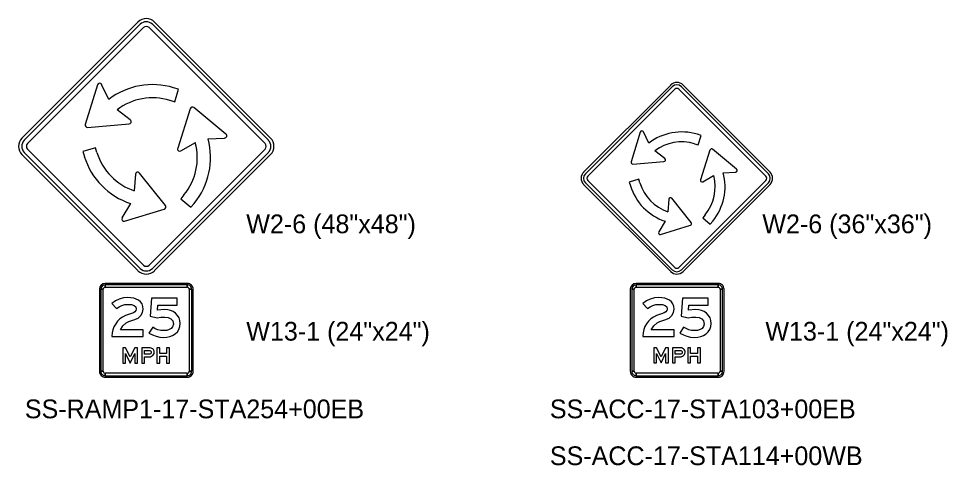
# Model space of a CAD drawing. Extents: x 620856.8 to 620948.6, y 415598.8 to 415658.2.
# Drawn here: x 620856.81 to 620876.63, y 415601 to 415610.53 of the extents above; entities that cross this region are included whole.
import ezdxf

# ---------------------------------------------------------------- set-up
doc = ezdxf.new("R2010")
doc.units = 0
doc.layers.add('SIGNS', color=7, linetype='Continuous')

msp = doc.modelspace()

# ---------------------------------------------------------------- linework, layer by layer
at = {"layer": 'SIGNS'}
for p, q in [((620856.878, 415607.977), (620859.353, 415610.452)), ((620856.926, 415607.93), (620859.4, 415610.405)), ((620859.471, 415610.334), (620856.996, 415607.859)), ((620862.064, 415607.859), (620859.589, 415610.334)), ((620859.66, 415610.405), (620862.135, 415607.93)), ((620859.707, 415610.452), (620862.182, 415607.977)), ((620858.489, 415609.113), (620858.229, 415608.266)), ((620858.489, 415609.113), (620858.229, 415608.266)), ((620858.73, 415608.799), (620858.578, 415609.12)), ((620858.73, 415608.799), (620858.578, 415609.12)), ((620868.863, 415607.252), (620870.72, 415609.108)), ((620868.899, 415607.216), (620870.755, 415609.072)), ((620870.808, 415609.019), (620868.952, 415607.163)), ((620872.752, 415607.163), (620870.896, 415609.019)), ((620870.949, 415609.072), (620872.805, 415607.216)), ((620870.985, 415609.108), (620872.841, 415607.252)), ((620859.188, 415608.363), (620858.907, 415608.58)), ((620859.188, 415608.363), (620858.907, 415608.58)), ((620860.47, 415608.603), (620860.2, 415607.759)), ((620860.47, 415608.603), (620860.2, 415607.759)), ((620861.231, 415608.061), (620860.547, 415608.626)), ((620861.231, 415608.061), (620860.547, 415608.626)), ((620858.279, 415608.204), (620859.163, 415608.277)), ((620858.279, 415608.204), (620859.163, 415608.277)), ((620860.847, 415607.959), (620861.202, 415607.976)), ((620860.847, 415607.959), (620861.202, 415607.976)), ((620870.071, 415608.104), (620869.876, 415607.468)), ((620870.071, 415608.104), (620869.876, 415607.468)), ((620870.252, 415607.868), (620870.138, 415608.109)), ((620870.252, 415607.868), (620870.138, 415608.109)), ((620856.996, 415607.741), (620859.471, 415605.266)), ((620859.589, 415605.266), (620862.064, 415607.741)), ((620860.27, 415607.703), (620860.577, 415607.879)), ((620860.27, 415607.703), (620860.577, 415607.879)), ((620872.127, 415607.315), (620871.615, 415607.738)), ((620872.127, 415607.315), (620871.615, 415607.738)), ((620859.353, 415605.149), (620856.878, 415607.623)), ((620859.4, 415605.196), (620856.926, 415607.671)), ((620862.135, 415607.671), (620859.66, 415605.196)), ((620862.182, 415607.623), (620859.707, 415605.149)), ((620870.596, 415607.541), (620870.385, 415607.703)), ((620870.596, 415607.541), (620870.385, 415607.703)), ((620871.557, 415607.721), (620871.354, 415607.088)), ((620871.557, 415607.721), (620871.354, 415607.088)), ((620869.914, 415607.422), (620870.576, 415607.476)), ((620869.914, 415607.422), (620870.576, 415607.476)), ((620859.297, 415607.204), (620859.275, 415606.85)), ((620859.297, 415607.204), (620859.275, 415606.85)), ((620859.939, 415606.541), (620859.383, 415607.231)), ((620859.939, 415606.541), (620859.383, 415607.231)), ((620871.407, 415607.046), (620871.637, 415607.178)), ((620871.407, 415607.046), (620871.637, 415607.178)), ((620871.84, 415607.238), (620872.106, 415607.251)), ((620871.84, 415607.238), (620872.106, 415607.251)), ((620870.72, 415605.13), (620868.863, 415606.986)), ((620870.755, 415605.166), (620868.899, 415607.022)), ((620868.952, 415607.075), (620870.808, 415605.219)), ((620870.896, 415605.219), (620872.752, 415607.075)), ((620872.805, 415607.022), (620870.949, 415605.166)), ((620872.841, 415606.986), (620870.985, 415605.13)), ((620859.193, 415606.581), (620859.012, 415606.275)), ((620859.193, 415606.581), (620859.012, 415606.275)), ((620870.678, 415606.672), (620870.661, 415606.406)), ((620870.678, 415606.672), (620870.661, 415606.406)), ((620871.159, 415606.174), (620870.742, 415606.692)), ((620871.159, 415606.174), (620870.742, 415606.692)), ((620859.068, 415606.204), (620859.915, 415606.464)), ((620859.068, 415606.204), (620859.915, 415606.464)), ((620870.599, 415606.204), (620870.464, 415605.975)), ((620870.599, 415606.204), (620870.464, 415605.975)), ((620870.505, 415605.922), (620871.141, 415606.117)), ((620870.505, 415605.922), (620871.141, 415606.117)), ((620858.53, 415604.752), (620858.53, 415603.002)), ((620858.561, 415604.752), (620858.613, 415604.752)), ((620860.405, 415604.877), (620858.655, 415604.877)), ((620858.655, 415604.794), (620858.655, 415604.846)), ((620860.405, 415604.846), (620860.405, 415604.794)), ((620860.447, 415604.752), (620860.499, 415604.752)), ((620860.53, 415603.002), (620860.53, 415604.752)), ((620869.859, 415604.753), (620869.859, 415603.003)), ((620869.89, 415604.753), (620869.943, 415604.753)), ((620871.734, 415604.878), (620869.984, 415604.878)), ((620869.984, 415604.794), (620869.984, 415604.846)), ((620871.734, 415604.846), (620871.734, 415604.794)), ((620871.776, 415604.753), (620871.828, 415604.753)), ((620871.859, 415603.003), (620871.859, 415604.753)), ((620858.613, 415603.002), (620858.561, 415603.002)), ((620860.499, 415603.002), (620860.447, 415603.002)), ((620869.943, 415603.003), (620869.89, 415603.003)), ((620871.828, 415603.003), (620871.776, 415603.003)), ((620858.655, 415602.909), (620858.655, 415602.961)), ((620858.655, 415602.877), (620860.405, 415602.877)), ((620860.405, 415602.961), (620860.405, 415602.909)), ((620869.984, 415602.909), (620869.984, 415602.961)), ((620869.984, 415602.878), (620871.734, 415602.878)), ((620871.734, 415602.961), (620871.734, 415602.909))]:
    msp.add_line(p, q, dxfattribs=at)
for points in [[(620860.031, 415608.782), (620860.136, 415608.75), (620860.218, 415609.019), (620860.114, 415609.051)], [(620860.031, 415608.782), (620860.136, 415608.75), (620860.218, 415609.019), (620860.114, 415609.051)], [(620871.228, 415607.855), (620871.306, 415607.831), (620871.368, 415608.033), (620871.29, 415608.057)], [(620871.228, 415607.855), (620871.306, 415607.831), (620871.368, 415608.033), (620871.29, 415608.057)], [(620858.478, 415607.668), (620858.446, 415607.772), (620858.177, 415607.689), (620858.209, 415607.585)], [(620858.478, 415607.668), (620858.446, 415607.772), (620858.177, 415607.689), (620858.209, 415607.585)], [(620870.063, 415607.02), (620870.039, 415607.098), (620869.837, 415607.036), (620869.861, 415606.958)], [(620870.063, 415607.02), (620870.039, 415607.098), (620869.837, 415607.036), (620869.861, 415606.958)], [(620860.334, 415606.763), (620860.264, 415606.679), (620860.481, 415606.5), (620860.551, 415606.584)], [(620860.334, 415606.763), (620860.264, 415606.679), (620860.481, 415606.5), (620860.551, 415606.584)], [(620871.455, 415606.341), (620871.403, 415606.278), (620871.566, 415606.144), (620871.618, 415606.207)], [(620871.455, 415606.341), (620871.403, 415606.278), (620871.566, 415606.144), (620871.618, 415606.207)], [(620859.432, 415603.179), (620859.489, 415603.179), (620859.489, 415603.31), (620859.585, 415603.31), (620859.617, 415603.313), (620859.645, 415603.322), (620859.667, 415603.337), (620859.684, 415603.359), (620859.695, 415603.383), (620859.699, 415603.408), (620859.697, 415603.429), (620859.691, 415603.447), (620859.681, 415603.464), (620859.668, 415603.479), (620859.652, 415603.491), (620859.634, 415603.499), (620859.614, 415603.505), (620859.592, 415603.506), (620859.432, 415603.506), (620859.432, 415603.179)], [(620859.489, 415603.365), (620859.489, 415603.449), (620859.587, 415603.449), (620859.606, 415603.446), (620859.622, 415603.438), (620859.633, 415603.424), (620859.637, 415603.407), (620859.633, 415603.39), (620859.623, 415603.377), (620859.608, 415603.368), (620859.59, 415603.365), (620859.489, 415603.365)], [(620870.761, 415603.18), (620870.819, 415603.18), (620870.819, 415603.31), (620870.914, 415603.31), (620870.946, 415603.313), (620870.974, 415603.322), (620870.996, 415603.338), (620871.013, 415603.359), (620871.024, 415603.383), (620871.028, 415603.408), (620871.026, 415603.429), (620871.02, 415603.447), (620871.01, 415603.464), (620870.997, 415603.479), (620870.981, 415603.491), (620870.963, 415603.5), (620870.943, 415603.505), (620870.921, 415603.506), (620870.761, 415603.506), (620870.761, 415603.18)], [(620870.819, 415603.365), (620870.819, 415603.449), (620870.916, 415603.449), (620870.935, 415603.446), (620870.951, 415603.438), (620870.962, 415603.425), (620870.966, 415603.407), (620870.962, 415603.39), (620870.952, 415603.377), (620870.937, 415603.368), (620870.919, 415603.365), (620870.819, 415603.365)]]:
    msp.add_lwpolyline(points, dxfattribs=at)
for points in [[(620858.561, 415604.752), (620858.561, 415603.002), (620858.613, 415603.002), (620858.613, 415604.752), (620858.561, 415604.752), (620858.561, 415604.752)], [(620860.405, 415604.846), (620858.655, 415604.846), (620858.655, 415604.794), (620860.405, 415604.794), (620860.405, 415604.846), (620860.405, 415604.846)], [(620860.499, 415603.002), (620860.499, 415604.752), (620860.447, 415604.752), (620860.447, 415603.002), (620860.499, 415603.002), (620860.499, 415603.002)], [(620869.89, 415604.753), (620869.89, 415603.003), (620869.943, 415603.003), (620869.943, 415604.753), (620869.89, 415604.753), (620869.89, 415604.753)], [(620871.734, 415604.846), (620869.984, 415604.846), (620869.984, 415604.794), (620871.734, 415604.794), (620871.734, 415604.846), (620871.734, 415604.846)], [(620871.828, 415603.003), (620871.828, 415604.753), (620871.776, 415604.753), (620871.776, 415603.003), (620871.828, 415603.003), (620871.828, 415603.003)], [(620858.797, 415603.742), (620859.464, 415603.742), (620859.464, 415603.887), (620858.977, 415603.887), (620859.03, 415603.97), (620859.102, 415604.035), (620859.16, 415604.063), (620859.266, 415604.1), (620859.356, 415604.139), (620859.416, 415604.191), (620859.452, 415604.256), (620859.464, 415604.326), (620859.458, 415604.386), (620859.439, 415604.439), (620859.407, 415604.484), (620859.363, 415604.52), (620859.264, 415604.561), (620859.14, 415604.575), (620859.044, 415604.567), (620858.955, 415604.544), (620858.872, 415604.505), (620858.797, 415604.451), (620858.898, 415604.341), (620858.95, 415604.38), (620859.008, 415604.408), (620859.072, 415604.424), (620859.142, 415604.43), (620859.218, 415604.424), (620859.273, 415604.405), (620859.306, 415604.374), (620859.317, 415604.33), (620859.31, 415604.301), (620859.289, 415604.274), (620859.254, 415604.253), (620859.194, 415604.231), (620859.087, 415604.193), (620859.024, 415604.159), (620858.968, 415604.119), (620858.919, 415604.071), (620858.877, 415604.016), (620858.841, 415603.954), (620858.816, 415603.89), (620858.801, 415603.824), (620858.797, 415603.754)], [(620859.588, 415603.818), (620859.661, 415603.778), (620859.738, 415603.749), (620859.817, 415603.732), (620859.899, 415603.726), (620859.968, 415603.73), (620860.033, 415603.744), (620860.091, 415603.767), (620860.145, 415603.799), (620860.193, 415603.844), (620860.228, 415603.896), (620860.249, 415603.955), (620860.256, 415604.022), (620860.249, 415604.086), (620860.231, 415604.144), (620860.199, 415604.195), (620860.155, 415604.241), (620860.105, 415604.275), (620860.05, 415604.299), (620859.989, 415604.314), (620859.922, 415604.319), (620859.77, 415604.303), (620859.779, 415604.415), (620860.188, 415604.415), (620860.191, 415604.559), (620859.641, 415604.559), (620859.615, 415604.178), (620859.762, 415604.141), (620859.841, 415604.154), (620859.928, 415604.159), (620859.999, 415604.15), (620860.055, 415604.124), (620860.095, 415604.076), (620860.108, 415604.011), (620860.093, 415603.954), (620860.064, 415603.917), (620860.022, 415603.891), (620859.966, 415603.875), (620859.897, 415603.87), (620859.838, 415603.875), (620859.78, 415603.888), (620859.723, 415603.911), (620859.667, 415603.944)], [(620870.126, 415603.742), (620870.793, 415603.742), (620870.793, 415603.887), (620870.306, 415603.887), (620870.359, 415603.97), (620870.431, 415604.035), (620870.489, 415604.063), (620870.596, 415604.1), (620870.685, 415604.139), (620870.746, 415604.192), (620870.781, 415604.257), (620870.793, 415604.327), (620870.787, 415604.387), (620870.768, 415604.439), (620870.736, 415604.484), (620870.692, 415604.52), (620870.593, 415604.562), (620870.469, 415604.575), (620870.373, 415604.567), (620870.284, 415604.544), (620870.201, 415604.505), (620870.126, 415604.451), (620870.227, 415604.341), (620870.279, 415604.38), (620870.337, 415604.408), (620870.401, 415604.424), (620870.471, 415604.43), (620870.548, 415604.424), (620870.602, 415604.405), (620870.635, 415604.374), (620870.646, 415604.33), (620870.639, 415604.301), (620870.618, 415604.274), (620870.583, 415604.253), (620870.523, 415604.231), (620870.416, 415604.194), (620870.353, 415604.159), (620870.297, 415604.119), (620870.248, 415604.071), (620870.206, 415604.016), (620870.17, 415603.955), (620870.145, 415603.891), (620870.13, 415603.824), (620870.126, 415603.754)], [(620870.918, 415603.818), (620870.991, 415603.778), (620871.067, 415603.749), (620871.146, 415603.732), (620871.228, 415603.726), (620871.298, 415603.731), (620871.362, 415603.744), (620871.421, 415603.767), (620871.474, 415603.799), (620871.522, 415603.844), (620871.557, 415603.896), (620871.578, 415603.955), (620871.585, 415604.022), (620871.579, 415604.086), (620871.56, 415604.144), (620871.528, 415604.195), (620871.484, 415604.241), (620871.434, 415604.275), (620871.379, 415604.299), (620871.318, 415604.314), (620871.251, 415604.319), (620871.1, 415604.303), (620871.109, 415604.415), (620871.517, 415604.415), (620871.52, 415604.559), (620870.97, 415604.559), (620870.944, 415604.178), (620871.091, 415604.141), (620871.17, 415604.154), (620871.257, 415604.159), (620871.328, 415604.15), (620871.384, 415604.124), (620871.424, 415604.077), (620871.438, 415604.011), (620871.422, 415603.955), (620871.393, 415603.918), (620871.351, 415603.891), (620871.295, 415603.876), (620871.226, 415603.87), (620871.167, 415603.875), (620871.109, 415603.889), (620871.052, 415603.912), (620870.996, 415603.944)], [(620859.032, 415603.179), (620859.089, 415603.179), (620859.089, 415603.381), (620859.186, 415603.179), (620859.284, 415603.381), (620859.284, 415603.179), (620859.342, 415603.179), (620859.342, 415603.506), (620859.284, 415603.506), (620859.186, 415603.314), (620859.089, 415603.506), (620859.032, 415603.506)], [(620859.758, 415603.179), (620859.816, 415603.179), (620859.816, 415603.323), (620859.964, 415603.323), (620859.964, 415603.179), (620860.025, 415603.179), (620860.025, 415603.506), (620859.964, 415603.506), (620859.964, 415603.382), (620859.816, 415603.382), (620859.816, 415603.506), (620859.758, 415603.506)], [(620870.361, 415603.18), (620870.419, 415603.18), (620870.419, 415603.381), (620870.515, 415603.18), (620870.613, 415603.381), (620870.613, 415603.18), (620870.671, 415603.18), (620870.671, 415603.506), (620870.613, 415603.506), (620870.515, 415603.314), (620870.418, 415603.506), (620870.361, 415603.506)], [(620871.088, 415603.18), (620871.145, 415603.18), (620871.145, 415603.323), (620871.293, 415603.323), (620871.293, 415603.18), (620871.355, 415603.18), (620871.355, 415603.506), (620871.293, 415603.506), (620871.293, 415603.382), (620871.145, 415603.382), (620871.145, 415603.506), (620871.088, 415603.506)], [(620858.655, 415602.909), (620860.405, 415602.909), (620860.405, 415602.961), (620858.655, 415602.961), (620858.655, 415602.909), (620858.655, 415602.909)], [(620869.984, 415602.909), (620871.734, 415602.909), (620871.734, 415602.961), (620869.984, 415602.961), (620869.984, 415602.909), (620869.984, 415602.909)]]:
    msp.add_lwpolyline(points, close=True, dxfattribs=at)
for centre, radius, start, end in [((620859.53, 415610.275), 0.25, 45, 135), ((620859.53, 415610.275), 0.183, 45, 135), ((620859.53, 415610.275), 0.0833, 45, 135), ((620858.535, 415609.099), 0.0483, 25.328, 162.9789), ((620858.535, 415609.099), 0.0483, 25.328, 162.9789), ((620859.666, 415607.588), 1.53, 72.9789, 127.6979), ((620859.666, 415607.588), 1.53, 72.9789, 127.6979), ((620870.852, 415608.975), 0.187, 45, 135), ((620870.852, 415608.975), 0.137, 45, 135), ((620870.852, 415608.975), 0.0625, 45, 135), ((620859.666, 415607.588), 1.248, 72.9789, 127.429), ((620859.666, 415607.588), 1.248, 72.9789, 127.429), ((620860.516, 415608.588), 0.0483, 50.4667, 162.221), ((620860.516, 415608.588), 0.0483, 50.4667, 162.221), ((620859.159, 415608.325), 0.0483, 274.7333, 52.3842), ((620859.159, 415608.325), 0.0483, 274.7333, 52.3842), ((620858.275, 415608.252), 0.0483, 162.9789, 274.7333), ((620858.275, 415608.252), 0.0483, 162.9789, 274.7333), ((620870.106, 415608.093), 0.0362, 25.328, 162.9789), ((620870.106, 415608.093), 0.0362, 25.328, 162.9789), ((620857.055, 415607.8), 0.25, 135, 225), ((620857.055, 415607.8), 0.183, 135, 225), ((620859.371, 415607.558), 1.53, 320.4667, 15.1857), ((620859.371, 415607.558), 1.53, 320.4667, 15.1857), ((620861.2, 415608.024), 0.0483, 272.8158, 50.4667), ((620861.2, 415608.024), 0.0483, 272.8158, 50.4667), ((620862.005, 415607.8), 0.183, 315, 45), ((620862.005, 415607.8), 0.25, 315, 45), ((620870.954, 415606.96), 1.147, 72.9789, 127.6979), ((620870.954, 415606.96), 1.147, 72.9789, 127.6979), ((620857.055, 415607.8), 0.0833, 135, 225), ((620860.246, 415607.744), 0.0483, 162.221, 299.8719), ((620860.246, 415607.744), 0.0483, 162.221, 299.8719), ((620859.371, 415607.558), 1.248, 320.4667, 14.9168), ((620859.371, 415607.558), 1.248, 320.4667, 14.9168), ((620862.005, 415607.8), 0.0833, 315, 45), ((620870.954, 415606.96), 0.936, 72.9789, 127.429), ((620870.954, 415606.96), 0.936, 72.9789, 127.429), ((620871.592, 415607.71), 0.0362, 50.4667, 162.221), ((620871.592, 415607.71), 0.0362, 50.4667, 162.221), ((620859.671, 415608.034), 1.53, 197.0618, 251.7808), ((620859.671, 415608.034), 1.53, 197.0618, 251.7808), ((620859.671, 415608.034), 1.248, 197.0618, 251.5119), ((620859.671, 415608.034), 1.248, 197.0618, 251.5119), ((620870.573, 415607.512), 0.0362, 274.7333, 52.3842), ((620870.573, 415607.512), 0.0362, 274.7333, 52.3842), ((620869.911, 415607.458), 0.0362, 162.9789, 274.7333), ((620869.911, 415607.458), 0.0362, 162.9789, 274.7333), ((620859.346, 415607.201), 0.0483, 38.8162, 176.467), ((620859.346, 415607.201), 0.0483, 38.8162, 176.467), ((620868.996, 415607.119), 0.187, 135, 225), ((620868.996, 415607.119), 0.137, 135, 225), ((620868.996, 415607.119), 0.0625, 135, 225), ((620870.733, 415606.937), 0.936, 320.4667, 14.9168), ((620870.733, 415606.937), 0.936, 320.4667, 14.9168), ((620870.733, 415606.937), 1.147, 320.4667, 15.1857), ((620870.733, 415606.937), 1.147, 320.4667, 15.1857), ((620872.104, 415607.287), 0.0362, 272.8158, 50.4667), ((620872.104, 415607.287), 0.0362, 272.8158, 50.4667), ((620872.708, 415607.119), 0.0625, 315, 45), ((620872.708, 415607.119), 0.137, 315, 45), ((620872.708, 415607.119), 0.187, 315, 45), ((620870.958, 415607.294), 1.147, 197.0618, 251.7808), ((620870.958, 415607.294), 1.147, 197.0618, 251.7808), ((620870.958, 415607.294), 0.936, 197.0618, 251.5119), ((620870.958, 415607.294), 0.936, 197.0618, 251.5119), ((620871.389, 415607.077), 0.0362, 162.221, 299.8719), ((620871.389, 415607.077), 0.0362, 162.221, 299.8719), ((620859.901, 415606.51), 0.0483, 287.0618, 38.8162), ((620859.901, 415606.51), 0.0483, 287.0618, 38.8162), ((620870.714, 415606.67), 0.0362, 38.8162, 176.467), ((620870.714, 415606.67), 0.0362, 38.8162, 176.467), ((620859.054, 415606.25), 0.0483, 149.4109, 287.0618), ((620859.054, 415606.25), 0.0483, 149.4109, 287.0618), ((620871.13, 415606.152), 0.0362, 287.0618, 38.8162), ((620871.13, 415606.152), 0.0362, 287.0618, 38.8162), ((620870.495, 415605.957), 0.0362, 149.4109, 287.0618), ((620870.495, 415605.957), 0.0362, 149.4109, 287.0618), ((620859.53, 415605.325), 0.25, 225, 315), ((620859.53, 415605.325), 0.183, 225, 315), ((620859.53, 415605.325), 0.0833, 225, 315), ((620870.852, 415605.263), 0.137, 225, 315), ((620870.852, 415605.263), 0.0625, 225, 315), ((620870.852, 415605.263), 0.187, 225, 315), ((620858.655, 415604.752), 0.125, 90.0002, 179.9998), ((620858.655, 415604.752), 0.0937, 90.0002, 179.9998), ((620858.655, 415604.752), 0.0417, 90.0002, 179.9998), ((620860.405, 415604.752), 0.125, 0, 90.0002), ((620860.405, 415604.752), 0.0937, 0, 90.0002), ((620860.405, 415604.752), 0.0417, 0, 90.0002), ((620869.984, 415604.753), 0.125, 90.0002, 179.9998), ((620869.984, 415604.753), 0.0937, 90.0002, 179.9998), ((620869.984, 415604.753), 0.0417, 90.0002, 179.9998), ((620871.734, 415604.753), 0.125, 0, 90.0002), ((620871.734, 415604.753), 0.0937, 0, 90.0002), ((620871.734, 415604.753), 0.0417, 0, 90.0002), ((620858.655, 415603.002), 0.125, 179.9998, 270.0001), ((620858.655, 415603.002), 0.0937, 179.9998, 270.0001), ((620858.655, 415603.002), 0.0417, 179.9998, 270.0001), ((620860.405, 415603.002), 0.125, 270.0001, 0.0003), ((620860.405, 415603.002), 0.0937, 270.0001, 0.0003), ((620860.405, 415603.002), 0.0417, 270.0001, 0.0003), ((620869.984, 415603.003), 0.125, 179.9998, 270.0001), ((620869.984, 415603.003), 0.0937, 179.9998, 270.0001), ((620869.984, 415603.003), 0.0417, 179.9998, 270.0001), ((620871.734, 415603.003), 0.125, 270.0001, 0.0003), ((620871.734, 415603.003), 0.0937, 270.0001, 0.0003), ((620871.734, 415603.003), 0.0417, 270.0001, 0.0003)]:
    msp.add_arc(centre, radius, start, end, dxfattribs=at)

# ---------------------------------------------------------------- texts
for s, p in [('W2-6 (48"x48")', (620861.664, 415605.947)), ('W2-6 (36"x36")', (620872.676, 415605.947)), ('W13-1 (24"x24")', (620861.664, 415603.657)), ('W13-1 (24"x24")', (620872.741, 415603.657)), ('SS-RAMP1-17-STA254+00EB', (620856.939, 415602.001)), ('SS-ACC-17-STA103+00EB', (620868.142, 415602.001)), ('SS-ACC-17-STA114+00WB', (620868.142, 415601.001))]:
    msp.add_text(s, height=0.4, rotation=0, dxfattribs=at).set_placement(p)

doc.saveas('drawing.dxf')
